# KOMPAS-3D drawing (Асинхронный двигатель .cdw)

Referenced files: Асинхронный двигатель (LT).cdw
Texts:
  Асинхронный двигатель 4А100S4У3 общий вид
  Электродвигатель Асинхронный двигатель 4А100S4У3
  Текст на чертеже
  Размерные надписи
  Шероховатость
  Линия-выноска #1
  Линия-выноска #2
  Линия-выноска #3
  Отклонения формы и база
  Заголовок таблицы
  Ячейка таблицы
  Стрелка вида
  Обозначение изменения
  Фигурная скобка
  Номер узла
  Марка координационной оси
  VRCB
  Выносная надпись
  Обозначение узла
  Марка/позиционное обозначение с линией-выноской
  Марка/позиционное обозначение на линии
  Марка/позиционное обозначение без линии-выноски
  кол-во
  Доп. указ.
  Позиц.
  Сборочный чертёж
  Документация
  Детали
  Станина
  Торцевой щит
  Вентилятор
  Выступающий конец вала
  Кожух
  Коробка выводов
  Сердечник статора
  Скоба
  Обмотка статора
  Сердечник ротора
  Короткозамыкающие кольца
  Балансировочные грузы
  Втулка
  Подшипниковая крышка
  Вентиляционные лопатки
  КП-2069829-1004-09-00
  Стандартные изделия
  Болт 2М6 15 ГОСТ7798-70
  Болт 2М5 8 ГОСТ7798-70
  Рым-болт М10 15 ГОСТ7781-70
  Подшипник 206 ГОСТ8338-75
  Стопорный винт М6 20
  ГОСТ17475-72
  Ст2013
  Асинхронный двигатель
  общий вид
Dimensions and other numbers on the sheet: 0; 7; 1; 12; 4; 19; 2; 17; 5; 3; 13; 9; 11; 14; 15; 21; 8; 18; 6; 83,5; 93; 228,3; 112; 147; 63; 160; 200; 231; 265; 235; 365; 20; 10; 4отв; 48; 110; 60; 16; 100; 1:1; 4А100S4У3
